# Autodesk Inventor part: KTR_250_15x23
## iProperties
Created: 2006-12
Part Number: KTR_250_15x23
Cost Center: 0 kg
Material: Stahl (schweißbar)
Document SubType Name: Modeling
Designer: Martin
Authority: 0 mm^3
Density: 7.86 g/cm^3
SaveDate: 2004-12-12
SaveTime: 22:14
TotalMass: 0 kg
TotalVolume: 0 mm^3
Author: Martin
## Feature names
1. Basis1
